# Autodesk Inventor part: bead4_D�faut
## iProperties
Created: 2011-01
Part Number: bead4_D�faut
Document SubType Name: Modeling
Designer: eric
Density: 1 g/cm^3
Mass: 0.0737828 g
Surface Area: 2.05652 cm^2
Volume: 0.0737828 cm^3
Author: eric
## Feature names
1. Base1
